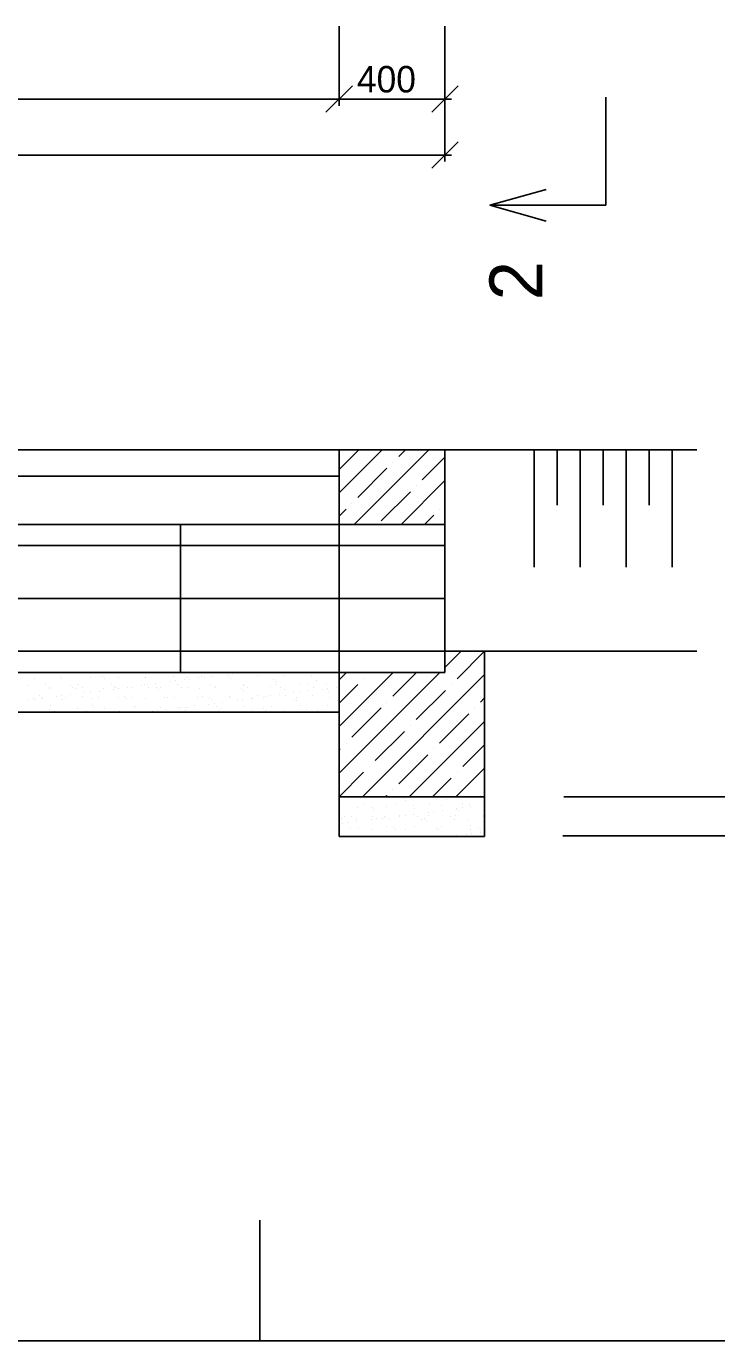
# Model space of a CAD drawing. Extents: x -2363 to 18637, y 14070 to 28920.
# Drawn here: x 7253 to 9865, y 14070 to 19039 of the extents above; entities that cross this region are included whole.
import ezdxf

# ---------------------------------------------------------------- set-up
doc = ezdxf.new("R2010")
doc.units = 0
for name, color, linetype in [('KÓTY', 7, 'Continuous'), ('OBRYS', 7, 'Continuous'), ('SJEZD', 7, 'Continuous'), ('ŠRAFY', 7, 'Continuous')]:
    doc.layers.add(name, color=color, linetype=linetype)

# ---------------------------------------------------------------- blocks, each defined once
blk = doc.blocks.new('_ARCHTICK')
blk.add_lwpolyline([(-0.5, -0.5), (0.5, 0.5)])

msp = doc.modelspace()

# ---------------------------------------------------------------- linework, layer by layer
for p, q in [((8136.7, 14070.3), (8136.7, 14526.5)), ((8136.7, 14070.3), (8136.7, 14526.5)), ((8136.7, 14070.3), (8136.7, 14514.6)), ((-2363.3, 14070.3), (18636.7, 14070.3))]:
    msp.add_line(p, q)
at = {"layer": 'KÓTY'}
for p, q in [((8437, 19039.2), (8437, 18739.1)), ((8437, 19039.2), (8437, 18739.1)), ((8837, 19039.2), (8837, 18739.1)), ((8837, 19039.2), (8837, 18527.6)), ((4212, 18764.1), (8462, 18764.1)), ((8412, 18764.1), (8862, 18764.1)), ((9446.2, 18362.8), (9446.2, 18770.8)), ((3812, 18552.6), (8862, 18552.6)), ((9006.9, 18362.8), (9219.5, 18422.8)), ((9006.9, 18362.8), (9219.5, 18302.8)), ((9446.2, 18362.8), (9006.9, 18362.8)), ((9287, 16126.4), (10294.7, 16126.4)), ((9287, 16126.4), (10294.7, 16126.4)), ((9283.6, 15979.1), (10294.7, 15979.1))]:
    msp.add_line(p, q, dxfattribs=at)
at = {"layer": 'OBRYS'}
for p, q in [((3837, 17438.6), (8837, 17438.6)), ((8837, 17438.6), (8837, 17076.4)), ((8837, 17076.4), (3837, 17076.4)), ((2883.8, 16676.4), (9790.2, 16676.4)), ((8987, 15976.4), (8987, 16676.4)), ((4240, 16447.5), (8437, 16446.4)), ((8437, 16446.4), (8437, 15976.4)), ((8437, 15976.4), (8987, 15976.4))]:
    msp.add_line(p, q, dxfattribs=at)
at = {"layer": 'SJEZD'}
for p, q in [((9790.2, 17438.6), (2883.8, 17438.6)), ((8437, 17156.4), (8437, 17438.6)), ((8837, 17156.4), (8837, 17438.6)), ((8437, 17338.6), (4237, 17338.6)), ((8837, 17156.4), (3837, 17156.4)), ((7837, 17156.4), (7837, 16596.4)), ((8437, 16596.4), (8437, 17156.4)), ((8837, 17156.4), (8837, 16596.4)), ((8837, 17076.4), (3837, 17076.4)), ((8837, 16876.4), (3837, 16876.4)), ((2883.8, 16676.4), (9790.2, 16676.4)), ((8837, 16676.4), (3837, 16676.4)), ((8837, 16615.2), (8898.2, 16676.4)), ((8883, 16572.8), (8986.6, 16676.4)), ((8987, 15976.4), (8987, 16676.4)), ((8837, 16596.4), (3837, 16596.4)), ((8437, 15976.4), (8437, 16596.4)), ((8437, 16568.7), (8464.7, 16596.4)), ((8437, 16391.9), (8641.4, 16596.4)), ((8437, 16215.2), (8818.2, 16596.4)), ((8551.6, 16594.9), (8553, 16596.4)), ((8640, 16506.5), (8729.8, 16596.4)), ((8437, 16480.3), (8507.4, 16550.7)), ((8525, 16126.4), (8987, 16588.4)), ((8529.5, 16572.8), (8529.5, 16572.8)), ((8860.9, 16550.7), (8860.9, 16550.7)), ((8728.3, 16418.1), (8838.8, 16528.6)), ((8971.4, 16484.4), (8987, 16500)), ((8485.3, 16351.8), (8595.8, 16462.3)), ((8617.9, 16484.4), (8617.9, 16484.4)), ((8949.3, 16462.3), (8949.3, 16462.3)), ((8437, 16446.4), (4237, 16446.4)), ((8701.8, 16126.4), (8987, 16411.6)), ((8816.7, 16329.7), (8927.2, 16440.2)), ((8573.7, 16263.5), (8684.2, 16373.9)), ((8706.3, 16396), (8706.3, 16396)), ((8437, 16303.5), (8441.1, 16307.7)), ((8463.2, 16329.7), (8463.2, 16329.7)), ((8794.6, 16307.7), (8794.6, 16307.7)), ((8905.1, 16241.4), (8987, 16323.2)), ((8662.1, 16175.1), (8772.5, 16285.6)), ((8437, 16126.8), (8529.5, 16219.3)), ((8551.6, 16241.4), (8551.6, 16241.4)), ((8878.5, 16126.4), (8987, 16234.8)), ((8883, 16219.3), (8883, 16219.3)), ((8640, 16153), (8640, 16153)), ((8790.2, 16126.4), (8860.9, 16197.2)), ((8437, 16126.4), (8987, 16126.4)), ((8613.4, 16126.4), (8617.9, 16130.9)), ((8971.4, 16130.9), (8971.4, 16130.9)), ((8437, 15976.4), (8987, 15976.4))]:
    msp.add_line(p, q, dxfattribs=at)
at = {"layer": 'ŠRAFY'}
for p, q in [((8437, 17275.8), (8599.7, 17438.6)), ((8437, 17364.2), (8511.3, 17438.6)), ((8494.3, 17156.4), (8776.5, 17438.6)), ((8662.1, 17412.5), (8688.1, 17438.6)), ((8750.4, 17324.1), (8837, 17410.7)), ((9174.4, 17438.6), (9174.4, 16994.6)), ((9261.4, 17229.1), (9261.4, 17438.6)), ((9348.4, 17438.6), (9348.4, 16994.6)), ((9435.5, 17229.1), (9435.5, 17438.6)), ((9522.5, 17438.6), (9522.5, 16994.6)), ((9609.5, 17229.1), (9609.5, 17438.6)), ((9696.6, 17438.6), (9696.6, 16994.6)), ((8507.4, 17257.8), (8617.9, 17368.3)), ((8640, 17390.4), (8640, 17390.4)), ((8671.1, 17156.4), (8837, 17322.3)), ((8728.3, 17302), (8728.3, 17302)), ((8595.8, 17169.4), (8706.3, 17279.9)), ((8437, 17187.4), (8463.2, 17213.6)), ((8485.3, 17235.7), (8485.3, 17235.7)), ((8816.7, 17213.6), (8816.7, 17213.6)), ((8759.5, 17156.4), (8794.6, 17191.5)), ((7262.3, 16546.8), (7262.3, 16546.8)), ((7285.8, 16572.5), (7285.8, 16572.5)), ((7326.2, 16550.2), (7326.2, 16550.2)), ((7382.6, 16581.9), (7382.6, 16581.9)), ((7388.1, 16572), (7388.1, 16572)), ((7450.7, 16550.4), (7450.7, 16550.4)), ((7496.1, 16575.9), (7496.1, 16575.9)), ((7542.6, 16580.6), (7542.6, 16580.6)), ((7550, 16573.8), (7550, 16573.8)), ((7575.3, 16550.6), (7575.3, 16550.6)), ((7600.8, 16577.2), (7600.8, 16577.2)), ((7690.7, 16547.4), (7690.7, 16547.4)), ((7699.8, 16550.8), (7699.8, 16550.8)), ((7703.2, 16576.7), (7703.2, 16576.7)), ((7705.1, 16577), (7705.1, 16577)), ((7711.5, 16550.1), (7711.5, 16550.1)), ((7744.1, 16554.4), (7744.1, 16554.4)), ((7798.4, 16561.6), (7798.4, 16561.6)), ((7811.2, 16580.6), (7811.2, 16580.6)), ((7819.2, 16564.3), (7819.2, 16564.3)), ((7824.4, 16551.1), (7824.4, 16551.1)), ((7851.7, 16568.6), (7851.7, 16568.6)), ((7865.1, 16575.6), (7865.1, 16575.6)), ((7872.5, 16568.9), (7872.5, 16568.9)), ((7906.1, 16575.8), (7906.1, 16575.8)), ((7915.9, 16581.9), (7915.9, 16581.9)), ((7926.9, 16578.5), (7926.9, 16578.5)), ((7949, 16551.3), (7949, 16551.3)), ((7959.4, 16582.8), (7959.4, 16582.8)), ((8013.7, 16589.9), (8013.7, 16589.9)), ((8018.2, 16581.5), (8018.2, 16581.5)), ((8027.5, 16572.1), (8027.5, 16572.1)), ((8034.6, 16592.7), (8034.6, 16592.7)), ((8073.5, 16551.5), (8073.5, 16551.5)), ((8126.3, 16585.3), (8126.3, 16585.3)), ((8187.6, 16570.7), (8187.6, 16570.7)), ((8195, 16564), (8195, 16564)), ((8198.1, 16551.7), (8198.1, 16551.7)), ((8231, 16586.7), (8231, 16586.7)), ((8285.1, 16549.2), (8285.1, 16549.2)), ((8322.7, 16552), (8322.7, 16552)), ((8333.3, 16586.2), (8333.3, 16586.2)), ((8350, 16567.2), (8350, 16567.2)), ((8389.8, 16550.5), (8389.8, 16550.5)), ((7279.2, 16500.5), (7279.2, 16500.5)), ((7302.2, 16510.3), (7302.2, 16510.3)), ((7309.5, 16503.6), (7309.5, 16503.6)), ((7313.4, 16497.7), (7313.4, 16497.7)), ((7339.9, 16535), (7339.9, 16535)), ((7343, 16539.4), (7343, 16539.4)), ((7367.7, 16504.9), (7367.7, 16504.9)), ((7388.5, 16507.6), (7388.5, 16507.6)), ((7403.7, 16500.7), (7403.7, 16500.7)), ((7421.1, 16511.9), (7421.1, 16511.9)), ((7422.4, 16545.4), (7422.4, 16545.4)), ((7429.8, 16538.7), (7429.8, 16538.7)), ((7444.6, 16536.3), (7444.6, 16536.3)), ((7464.6, 16506.8), (7464.6, 16506.8)), ((7467.6, 16539.6), (7467.6, 16539.6)), ((7475.4, 16519.1), (7475.4, 16519.1)), ((7496.2, 16521.8), (7496.2, 16521.8)), ((7498.7, 16498.8), (7498.7, 16498.8)), ((7528.3, 16501), (7528.3, 16501)), ((7528.7, 16526.1), (7528.7, 16526.1)), ((7546.9, 16535.8), (7546.9, 16535.8)), ((7583.1, 16533.2), (7583.1, 16533.2)), ((7584.8, 16541.9), (7584.8, 16541.9)), ((7592.2, 16539.9), (7592.2, 16539.9)), ((7603.4, 16500.1), (7603.4, 16500.1)), ((7603.9, 16536), (7603.9, 16536)), ((7624.6, 16505.4), (7624.6, 16505.4)), ((7632, 16498.7), (7632, 16498.7)), ((7636.4, 16540.3), (7636.4, 16540.3)), ((7652.9, 16501.2), (7652.9, 16501.2)), ((7654.9, 16539.7), (7654.9, 16539.7)), ((7705.7, 16499.6), (7705.7, 16499.6)), ((7716.7, 16540.1), (7716.7, 16540.1)), ((7744.9, 16540.5), (7744.9, 16540.5)), ((7752.2, 16533.8), (7752.2, 16533.8)), ((7759.6, 16541), (7759.6, 16541)), ((7777.4, 16501.4), (7777.4, 16501.4)), ((7787, 16501.9), (7787, 16501.9)), ((7813.7, 16503.5), (7813.7, 16503.5)), ((7841.3, 16540.3), (7841.3, 16540.3)), ((7862, 16540.5), (7862, 16540.5)), ((7902, 16501.6), (7902, 16501.6)), ((7907.3, 16537), (7907.3, 16537)), ((7918.4, 16504.9), (7918.4, 16504.9)), ((7947.1, 16500.5), (7947.1, 16500.5)), ((7965.8, 16540.5), (7965.8, 16540.5)), ((7970, 16544.4), (7970, 16544.4)), ((8020.8, 16504.4), (8020.8, 16504.4)), ((8026.6, 16501.9), (8026.6, 16501.9)), ((8067.3, 16535.6), (8067.3, 16535.6)), ((8074.7, 16545.8), (8074.7, 16545.8)), ((8074.7, 16528.9), (8074.7, 16528.9)), ((8090.4, 16540.8), (8090.4, 16540.8)), ((8104, 16498.2), (8104, 16498.2)), ((8109.5, 16497), (8109.5, 16497)), ((8128.8, 16508.3), (8128.8, 16508.3)), ((8151.1, 16502.1), (8151.1, 16502.1)), ((8158.3, 16505.4), (8158.3, 16505.4)), ((8177, 16545.3), (8177, 16545.3)), ((8179.1, 16508.1), (8179.1, 16508.1)), ((8211.6, 16512.4), (8211.6, 16512.4)), ((8215, 16541), (8215, 16541)), ((8229.8, 16532.1), (8229.8, 16532.1)), ((8233.5, 16509.6), (8233.5, 16509.6)), ((8266, 16519.6), (8266, 16519.6)), ((8275.7, 16502.3), (8275.7, 16502.3)), ((8286.8, 16522.3), (8286.8, 16522.3)), ((8319.3, 16526.6), (8319.3, 16526.6)), ((8335.8, 16509.1), (8335.8, 16509.1)), ((8339.5, 16541.2), (8339.5, 16541.2)), ((8373.6, 16533.7), (8373.6, 16533.7)), ((8389.8, 16530.7), (8389.8, 16530.7)), ((8394.5, 16536.5), (8394.5, 16536.5)), ((8397.2, 16524), (8397.2, 16524)), ((8400.3, 16502.5), (8400.3, 16502.5)), ((8427, 16540.8), (8427, 16540.8)), ((7260, 16490.7), (7260, 16490.7)), ((7280.9, 16493.4), (7280.9, 16493.4)), ((7288.3, 16495.4), (7288.3, 16495.4)), ((7342.4, 16457.9), (7342.4, 16457.9)), ((7344.3, 16471.7), (7344.3, 16471.7)), ((7358.5, 16450), (7358.5, 16450)), ((7390.6, 16494.9), (7390.6, 16494.9)), ((7447.1, 16459.2), (7447.1, 16459.2)), ((7483, 16450.2), (7483, 16450.2)), ((7504.4, 16470.3), (7504.4, 16470.3)), ((7511.8, 16463.6), (7511.8, 16463.6)), ((7549.4, 16458.7), (7549.4, 16458.7)), ((7607.6, 16450.5), (7607.6, 16450.5)), ((7657.5, 16462.6), (7657.5, 16462.6)), ((7666.8, 16466.8), (7666.8, 16466.8)), ((7727.6, 16448.7), (7727.6, 16448.7)), ((7732.2, 16450.7), (7732.2, 16450.7)), ((7748.4, 16451.4), (7748.4, 16451.4)), ((7762.2, 16464), (7762.2, 16464)), ((7780.9, 16455.7), (7780.9, 16455.7)), ((7826.9, 16465.4), (7826.9, 16465.4)), ((7834.2, 16458.7), (7834.2, 16458.7)), ((7835.3, 16462.9), (7835.3, 16462.9)), ((7856.1, 16465.6), (7856.1, 16465.6)), ((7856.7, 16450.9), (7856.7, 16450.9)), ((7864.5, 16463.5), (7864.5, 16463.5)), ((7888.6, 16469.9), (7888.6, 16469.9)), ((7942.9, 16477), (7942.9, 16477)), ((7954.5, 16493.8), (7954.5, 16493.8)), ((7963.8, 16479.8), (7963.8, 16479.8)), ((7972.5, 16467.4), (7972.5, 16467.4)), ((7981.3, 16451.1), (7981.3, 16451.1)), ((7989.3, 16461.9), (7989.3, 16461.9)), ((7996.3, 16484.1), (7996.3, 16484.1)), ((8050.6, 16491.2), (8050.6, 16491.2)), ((8071.4, 16494), (8071.4, 16494)), ((8077.2, 16468.7), (8077.2, 16468.7)), ((8105.9, 16451.4), (8105.9, 16451.4)), ((8149.3, 16460.5), (8149.3, 16460.5)), ((8156.7, 16453.7), (8156.7, 16453.7)), ((8179.5, 16468.2), (8179.5, 16468.2)), ((8230.4, 16451.6), (8230.4, 16451.6)), ((8269.6, 16495.6), (8269.6, 16495.6)), ((8276.9, 16488.8), (8276.9, 16488.8)), ((8287.6, 16472.1), (8287.6, 16472.1)), ((8311.7, 16457), (8311.7, 16457)), ((8355, 16451.8), (8355, 16451.8)), ((8392.3, 16473.4), (8392.3, 16473.4)), ((8432, 16492.1), (8432, 16492.1)), ((8519.4, 16121.4), (8519.4, 16121.4)), ((8529.5, 16101.9), (8529.5, 16101.9)), ((8654.1, 16102.1), (8654.1, 16102.1)), ((8679.5, 16120), (8679.5, 16120)), ((8686.9, 16113.2), (8686.9, 16113.2)), ((8778.6, 16102.3), (8778.6, 16102.3)), ((8841.9, 16116.4), (8841.9, 16116.4)), ((8903.2, 16102.6), (8903.2, 16102.6)), ((8439, 16049.8), (8439, 16049.8)), ((8459, 16050.6), (8459, 16050.6)), ((8484.2, 16051.2), (8484.2, 16051.2)), ((8507.2, 16087.6), (8507.2, 16087.6)), ((8559.3, 16084.9), (8559.3, 16084.9)), ((8563.7, 16051.9), (8563.7, 16051.9)), ((8566.6, 16078.1), (8566.6, 16078.1)), ((8608.8, 16051.4), (8608.8, 16051.4)), ((8615.2, 16091.5), (8615.2, 16091.5)), ((8665.7, 16054.4), (8665.7, 16054.4)), ((8666, 16051.4), (8666, 16051.4)), ((8686.5, 16057.1), (8686.5, 16057.1)), ((8719, 16061.4), (8719, 16061.4)), ((8719.9, 16092.8), (8719.9, 16092.8)), ((8721.7, 16081.3), (8721.7, 16081.3)), ((8733.3, 16051.6), (8733.3, 16051.6)), ((8773.4, 16068.5), (8773.4, 16068.5)), ((8774, 16055.3), (8774, 16055.3)), ((8794.2, 16071.3), (8794.2, 16071.3)), ((8822.3, 16092.3), (8822.3, 16092.3)), ((8826.7, 16075.6), (8826.7, 16075.6)), ((8857.9, 16051.8), (8857.9, 16051.8)), ((8878.7, 16056.6), (8878.7, 16056.6)), ((8881, 16082.7), (8881, 16082.7)), ((8881.7, 16080), (8881.7, 16080)), ((8889.1, 16073.2), (8889.1, 16073.2)), ((8901.9, 16085.5), (8901.9, 16085.5)), ((8930.3, 16096.2), (8930.3, 16096.2)), ((8934.4, 16089.7), (8934.4, 16089.7)), ((8981.1, 16056.2), (8981.1, 16056.2)), ((8982.5, 16052.1), (8982.5, 16052.1)), ((8437.2, 16001.5), (8437.2, 16001.5)), ((8446.4, 16043), (8446.4, 16043)), ((8450.4, 16026), (8450.4, 16026)), ((8471.2, 16028.8), (8471.2, 16028.8)), ((8481.2, 16011.1), (8481.2, 16011.1)), ((8501.1, 16040.4), (8501.1, 16040.4)), ((8503.7, 16033), (8503.7, 16033)), ((8509.7, 16010.5), (8509.7, 16010.5)), ((8558, 16040.2), (8558, 16040.2)), ((8561.8, 16001.7), (8561.8, 16001.7)), ((8578.9, 16042.9), (8578.9, 16042.9)), ((8601.4, 16046.2), (8601.4, 16046.2)), ((8611.4, 16047.2), (8611.4, 16047.2)), ((8617.8, 16014.4), (8617.8, 16014.4)), ((8625.6, 16040.6), (8625.6, 16040.6)), ((8641.2, 16009.7), (8641.2, 16009.7)), ((8648.6, 16003), (8648.6, 16003)), ((8686.4, 16001.9), (8686.4, 16001.9)), ((8722.5, 16015.7), (8722.5, 16015.7)), ((8750.2, 16040.9), (8750.2, 16040.9)), ((8761.5, 16044.9), (8761.5, 16044.9)), ((8768.9, 16038.1), (8768.9, 16038.1)), ((8803.7, 16006.2), (8803.7, 16006.2)), ((8810.9, 16002.2), (8810.9, 16002.2)), ((8824.8, 16015.2), (8824.8, 16015.2)), ((8874.8, 16041.1), (8874.8, 16041.1)), ((8923.9, 16041.3), (8923.9, 16041.3)), ((8932.8, 16019.1), (8932.8, 16019.1)), ((8935.5, 16002.4), (8935.5, 16002.4)), ((8963.7, 16004.8), (8963.7, 16004.8)), ((8776.6, 15978.2), (8776.6, 15978.2)), ((8863.6, 15976.9), (8863.6, 15976.9)), ((8881.3, 15979.6), (8881.3, 15979.6)), ((8917.9, 15984), (8917.9, 15984)), ((8938.7, 15986.7), (8938.7, 15986.7)), ((8971.1, 15998.1), (8971.1, 15998.1)), ((8971.3, 15991), (8971.3, 15991)), ((8983.6, 15979.1), (8983.6, 15979.1))]:
    msp.add_line(p, q, dxfattribs=at)

# ---------------------------------------------------------------- block references
at = {"layer": 'KÓTY', "xscale": 100, "yscale": 100}
for p in [(8437, 18764.1), (8837, 18764.1), (8837, 18552.6)]:
    msp.add_blockref('_ARCHTICK', p, dxfattribs=at)
at = {"layer": 'KÓTY', "xscale": 100, "yscale": 100, "rotation": 180}
msp.add_blockref('_ARCHTICK', (8437, 18764.1), dxfattribs=at)

# ---------------------------------------------------------------- texts
at = {"layer": 'KÓTY'}
msp.add_text('400', height=100, dxfattribs=at).set_placement((8504.3, 18789.1))
msp.add_text('2', height=200, rotation=90, dxfattribs=at).set_placement((9205.6, 18003.1))

doc.saveas('drawing.dxf')
